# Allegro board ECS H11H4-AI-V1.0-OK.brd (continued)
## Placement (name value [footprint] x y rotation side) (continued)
R156  -  [R0402_2]  174.28 171.39 90 top
R157  -  [R0402_2]  175.36 171.39 270 top
R158  -  [R0402_2]  176.51 171.39 90 top
R159  -  [R0402_2]  177.58 171.39 90 top
R160  -  [R0402_2]  179.05 171.39 270 top
R161  -  [R0402_2]  171.04 171.33 90 top
R162  -  [R0402_2]  172.12 171.33 270 top
R163  -  [R0402_2]  163.81 171.27 270 top
R164  -  [R0402_2]  164.95 171.27 90 top
R165  -  [R0402_2]  166.09 171.27 90 top
R166  -  [R0402_2]  167.23 171.27 90 top
R167  -  [R0402_2]  168.38 171.27 270 top
R168  -  [R0402_2]  103.73 171.27 180 top
R169  -  [R0402_2]  106.59 171.27 0 top
R170  -  [R0805_2]  52.43 171.07 180 top
R171  -  [R0402_2]  103.73 170.19 0 top
R172  -  [R0805_2]  14.45 169.61 180 top
R173  -  [R0402_2]  100.56 169.61 90 top
R174  -  [R0402_2]  102.15 169.61 90 top
R175  -  [R0805_2]  170.66 169.36 0 top
R176  -  [R0402_2]  174.28 169.3 90 top
R177  -  [R0402_2]  176.89 168.98 270 top
R178  -  [R0402_2]  116.88 168.73 180 top
R179  -  [R0402_2]  133.83 168.34 0 top
R180  -  [R0402_2]  35.85 158.69 0 top
R181  -  [R0805_2]  114.85 167.14 270 top
R182  -  [R0805_2]  120.69 166.95 270 top
R183  -  [R0805_2]  140.06 166.95 270 top
R184  -  [R0805_2]  133.39 166.82 180 top
R186  -  [R0402_2]  63.86 166.19 180 top
R187  -  [R0603_2]  96.43 165.99 180 top
R188  -  [R0402_2]  98.91 165.99 180 top
R189  -  [R0805_2]  107.48 165.87 90 top
R190  -  [R0402_2]  33.57 164.47 180 top
R191  -  [R0402_2]  35.79 161.74 180 top
R192  -  [R0805_2]  133.39 164.66 180 top
R193  -  [R0402_2]  54.27 164.6 180 top
R194  -  [R0402_2]  33.57 161.23 0 top
R195  -  [R0402_2]  37.44 162.5 270 top
R196  -  [R0805_2]  130.28 164.03 270 top
R197  -  [R0805_2]  148.76 164.03 270 top
R198  -  [R0402_2]  128.75 163.33 90 top
R199  -  [R0402_2]  146.03 162.82 0 top
R200  -  [R0402_2]  33.57 162.31 180 top
R201  -  [R0402_2]  83.29 162.38 90 top
R202  -  [R0402_2]  84.37 162.38 90 top
R203  -  [R0402_2]  85.45 162.38 270 top
R204  -  [R0402_2]  86.53 162.38 90 top
R205  -  [R0402_2]  87.61 162.38 90 top
R206  -  [R0603-SHORT_2-NMNP]  4.74 162.31 270 top
R208  -  [R0805_2]  100.5 160.98 0 top
R209  -  [R0402_2]  81.51 160.6 180 top
R210  -  [R0402_2]  85.95 160.6 0 top
R211  -  [R0402_2]  89.19 160.6 180 top
R212  -  [R0805_2]  38.96 164.03 90 top
R213  -  [R0603_2]  62.65 159.71 0 top
R214  -  [R0402_2]  80.43 159.52 180 top
R215  -  [R0402_2]  87.1 159.52 180 top
R216  -  [R0402_2]  89.19 159.52 180 top
R217  -  [R0402_2]  57.95 159.33 270 top
R218  -  [R0805_2]  114.34 158.76 0 top
R219  -  [R0402_2]  88.24 158.44 180 top
R221  -  [R0402_2]  89.26 157.36 180 top
R222  -  [R0402_2]  77.83 156.91 0 top
R223  -  [R0402_2]  55.35 156.53 270 top
R224  -  [R0402_2]  56.43 156.53 270 top
R225  -  [R0402_2]  58.27 156.53 90 top
R226  -  [R0402_2]  59.35 156.53 270 top
R227  -  [R0402_2]  92.37 156.41 180 top
R228  -  [R1206]  118.47 156.41 0 top
R229  -  [R1206]  136.56 156.41 0 top
R230  -  [R0402_2]  90.27 156.28 180 top
R231  -  [R0402_2]  76.75 155.83 180 top
R232  -  [R0402_2]  91.35 155.2 180 top
R233  -  [R0402_2]  75.67 154.76 180 top
R234  -  [R0402_2]  92.43 154.12 180 top
R235  -  [R0402_2]  74.08 152.6 0 top
R236  -  [R0402_2]  7.72 152.28 90 top
R237  -  [R0402_2]  8.8 152.28 90 top
R238  -  [R0402_2]  74.08 151.52 0 top
R239  -  [R1206]  177.65 151.45 270 top
R240  -  [R0805_2]  185.9 151.14 90 top
R241  -  [R0402_2]  6.58 149.48 270 top
R242  -  [R0402_2]  10.96 145.61 270 top
R243  -  [R0402_2]  184.25 143.9 270 top
R244  -  [R0402_2]  9.88 143.45 270 top
R245  -  [R0805_2]  185.14 141.86 180 top
R246  -  [R0402_2]  10.41 141.55 0 top
R247  -  [R0402_2]  10.41 140.4 0 top
R248  -  [R0402_2]  80.37 139.77 90 top
R249  -  [R0402_2]  81.45 139.77 270 top
R250  -  [R0402_2]  86.65 139.77 270 top
R251  -  [R0402_2]  10.41 139.26 0 top
R252  -  [R0402_2]  74.91 138.37 270 top
R253  -  [R0402_2]  77.06 138.37 90 top
R254  -  [R0402_2]  78.21 138.37 270 top
R255  -  [R0805_2]  185.14 138.37 180 top
R256  -  [R0402_2]  86.97 138.18 0 top
R257  -  [R0402_2]  10.41 138.12 0 top
R258  -  [R0402_2]  162.09 137.67 180 top
R259  -  [R0402_2]  166.85 137.67 180 top
R260  -  [R0402_2]  86.97 137.1 0 top
R261  -  [R0402_2]  162.09 136.59 180 top
R262  -  [R0402_2]  164.76 136.59 180 top
R263  -  [R0603_2]  72.43 136.34 180 top
R264  -  [R0402_2]  188 136.02 90 top
R265  -  [R0805_2]  189.52 136.02 270 top
R266  -  [R0402_2]  162.09 135.51 180 top
R267  -  [R0402_2]  164.76 135.51 180 top
R268  -  [R0805_2]  185.9 135.51 90 top
R269  -  [R0402_2]  10.45 135.07 0 top
R270  -  [R0402_2]  162.09 134.44 180 top
R271  -  [R0402_2]  72.24 133.93 180 top
R272  -  [R0603_2]  82.53 133.48 0 top
R273  -  [R1206]  177.65 132.97 270 top
R274  -  [R0402_2]  10.01 132.09 270 top
R275  -  [R0402_2]  11.09 132.09 90 top
R276  -  [R0805_2]  72.81 131.2 0 top
R277  -  [R0402_2]  5.18 130.12 90 top
R278  -  [R0402_2]  184.38 126.75 270 top
R279  -  [R0402_2]  5.18 126.43 90 top
R280  -  [R0805_2]  185.27 124.72 180 top
R281  -  [R0402_2]  84.68 123.77 0 top
R282  -  [R0402_2]  5.18 122.88 90 top
R283  -  [R0402_2]  83.11 122.65 270 top
R284  -  [R0402_2]  84.68 122.5 180 top
R285  -  [R0805_2]  185.27 121.23 180 top
R286  -  [R0805_2]  189.59 119.58 180 top
R287  -  [R0402_2]  5.18 119.26 90 top
R288  -  [R0402_2]  187.3 118.75 90 top
R289  -  [R0402_2]  114.21 118.5 270 top
R290  -  [R0402_2]  115.29 118.5 90 top
R291  -  [R0402_2]  116.37 118.5 270 top
R292  -  [R0402_2]  117.45 118.48 270 top
R293  -  [R0402_2]  10.71 118.24 0 top
R294  -  [R0603_2]  42.39 116.85 90 top
R295  -  [R0402_2]  45.19 115.31 270 top
R296  -  [R0402_2]  50.62 114.2 270 top
R297  -  [R0402_2]  48.93 114.18 90 top
R298  -  [R0402_2]  52.49 114.18 90 top
R299  -  [R0402_2]  53.57 114.18 90 top
R300  -  [R0402_2]  46.74 113.84 270 top
R301  -  [R0402_2]  37.31 113.61 0 top
R302  -  [R0402_2]  37.31 112.53 0 top
R303  -  [R0402_2]  5.69 112.21 0 top
R304  -  [R0402_2]  7.72 112.21 180 top
R305  -  [R0402_2]  9.75 112.21 0 top
R306  -  [R0603_2]  39.03 111.83 270 top
R307  -  [R0402_2]  44.67 111.48 270 top
R308  -  [R0402_2]  45.73 111.48 90 top
R309  -  [R0402_2]  37.31 111.45 0 top
R310  -  [R0402_2]  49.51 111.45 90 top
R311  -  [R0402_2]  46.9 111.38 270 top
R312  -  [R0402_2]  47.98 111.38 270 top
R313  -  [R0402_2]  52.49 111.32 270 top
R314  -  [R0402_2]  53.57 111.32 90 top
R315  -  [R0402_2]  60.49 111.31 180 top
R316  -  [R0402_2]  5.18 110.56 270 top
R317  -  [R0402_2]  6.26 110.56 90 top
R318  -  [R0402_2]  11.66 110.37 90 top
R319  -  [R0402_2]  7.85 109.86 180 top
R320  -  [R0603_2]  57.94 108.91 90 top
R321  -  [R0402_2]  114.15 108.91 270 top
R322  -  [R0402_2]  32.61 107 270 top
R323  -  [R0402_2]  48.81 106.37 90 top
R324  -  [R0402_2]  49.89 106.37 90 top
R325  -  [R0402_2]  50.97 106.37 90 top
R326  -  [R0402_2]  40.93 106.3 270 top
R327  -  [R0402_2]  64.94 105.73 270 top
R328  -  [R0402_2]  185.84 105.03 270 top
R329  -  [R0402_2]  32.61 104.59 90 top
R330  -  [R0402_2]  8.99 103.7 0 top
R331  -  [R1206]  178.03 103.13 90 top
R332  -  [R0805_2]  187.05 103 180 top
R333  -  [R0402_2]  29.95 102.88 0 top
R334  -  [R0402_2]  30.65 104.46 270 top
R335  -  [R0402_2]  31.53 102.37 270 top
R336  -  [R0402_2]  32.61 102.37 270 top
R337  -  [R0402_2]  8.48 102.11 90 top
R338  -  [R0805_2]  194.92 101.61 90 top
R339  -  [R0402_2]  64.94 101.22 90 top
R340  -  [R0805_2]  185.08 100.53 180 top
R341  -  [R0402_2]  5.94 99.76 90 top
R342  -  [R0402_2]  7.02 99.76 90 top
R343  -  [R0402-SHORT_2]  28.55 99.7 270 top
R344  -  [R0402_2]  32.23 99.64 270 top
R345  -  [R0805_2]  192.32 99.64 90 top
R346  -  [R0805_2]  194.92 98.11 270 top
R347  -  [R0402_2]  190.09 97.35 180 top
R348  -  [R0805_2]  185.08 97.22 180 top
R349  -  [R0402_2]  181.27 94.68 270 top
R350  -  [R0402_2]  190.67 94.68 270 top
R351  -  [R0402_2]  191.75 94.68 270 top
R352  -  [R0402_2]  6.2 93.06 180 top
R353  -  [R0402_2]  181.84 91.26 180 top
R354  -  [R0402_2]  64.94 92.02 90 top
R355  -  [R0402_2]  191.24 91.26 180 top
R356  -  [R0402_2]  6.2 90.87 180 top
R357  -  [R0402_2]  191.24 89.99 180 top
R358  -  [R0402_2]  32.17 89.79 0 top
R359  -  [R0402_2]  191.24 88.78 180 top
R360  -  [R0402_2]  32.17 88.72 0 top
R361  -  [R0402_2]  185.01 86.43 0 top
R362  -  [R0402_2]  187.68 86.43 0 top
R363  -  [R0402_2]  185.01 85.29 0 top
R364  -  [R0402_2]  187.68 85.29 180 top
R365  -  [R0402_2]  29.38 84.63 180 top
R366  -  [R0402_2]  187.68 84.21 180 top
R367  -  [R0402_2]  22.14 82.62 90 top
R368  -  [R0402_2]  23.22 82.62 90 top
R369  -  [R0402_2]  24.49 82.62 90 top
R370  -  [R0402_2]  11.66 82.49 270 top
R371  -  [R0402_2]  31.32 82.43 180 top
R372  -  [R0402_2]  31.32 81.36 180 top
R373  -  [R0402_2]  28.7 80.59 270 top
R374  -  [R0402_2]  22.64 79.19 0 top
R375  -  [R0402_2]  22.64 78.11 180 top
R376  -  [R0402_2]  29.82 77.73 180 top
R377  -  [R0402_2]  32.23 76.97 180 top
R378  -  [R0402_2]  29.82 76.65 180 top
R379  -  [R0402_2]  22.64 75.95 180 top
R380  -  [R0402_2]  32.23 75.89 180 top
R381  -  [R0402_2]  29.82 75.57 180 top
R382  -  [R0402_2]  22.64 74.87 180 top
R383  -  [R0402_2]  32.23 74.81 0 top
R384  -  [R0402_2]  22.64 73.79 180 top
R385  -  [R0402_2]  22.64 72.71 0 top
R386  -  [R0402_2]  29.31 72.65 270 top
R387  -  [R0402_2]  41.82 72.08 90 top
R388  -  [R0402_2]  43.98 72.08 270 top
R389  -  [R0402_2]  45.06 72.08 270 top
R390  -  [R0402_2]  47.6 72.08 270 top
R391  -  [R0402_2]  49.06 72.08 270 top
R392  -  [R0402_2]  50.65 72.08 270 top
R393  -  [R0402_2]  40.74 72.07 90 top
R394  -  [R0402_2]  39.67 72.04 90 top
R395  -  [R0402_2]  51.79 72.01 270 top
R396  -  [R0402_2]  52.87 72.01 90 top
R397  -  [R0402_2]  25.57 71.89 270 top
R398  -  [R0402_2]  26.77 71.89 90 top
R399  -  [R0603_2]  38.25 71.66 90 top
R400  -  [R0402_2]  22.64 71.44 180 top
R401  -  [R0402_2]  32.23 71.32 180 top
R402  -  [R0402_2]  22.64 70.36 0 top
R403  -  [R0402_2]  25.06 69.54 270 top
R404  -  [R0402_2]  39.66 69.54 270 top
R405  -  [R0402_2]  40.74 69.54 270 top
R406  -  [R0402_2]  41.82 69.54 90 top
R407  -  [R0402_2]  44.23 69.54 270 top
R408  -  [R0603_2]  65.06 69.47 270 top
R409  -  [R0402_2]  46.39 69.35 270 top
R410  -  [R0402_2]  47.6 69.35 270 top
R411  -  [R0402_2]  49 69.35 90 top
R412  -  [R0402_2]  50.08 69.35 270 top
R413  -  [R0402_2]  51.79 69.35 270 top
R414  -  [R0402_2]  52.87 69.35 90 top
R415  -  [R0402_2]  22.64 69.28 0 top
R416  -  [R0603_2]  43.03 69.16 90 top
R417  -  [R0603_2]  35.66 68.46 180 top
R421  -  [R0402_2]  33.31 67.25 0 top
R422  -  [R0402_2]  46.39 66.93 270 top
R423  -  [R0402_2]  49 66.93 270 top
R424  -  [R0402_2]  50.08 66.93 270 top
R425  -  [R0402_2]  37.12 66.74 270 top
R426  -  [R0402_2]  38.2 66.74 270 top
R427  -  [R0402_2]  39.66 66.74 270 top
R428  -  [R0402_2]  40.74 66.74 90 top
R429  -  [R0402_2]  36.04 66.74 270 top
R430  -  [R0402_2]  33.31 66.17 180 top
R431  -  [R0402_2]  25.88 64.59 90 top
R432  -  [R0402_2]  25.88 62.49 90 top
R433  -  [R0402_2]  185.08 61.16 0 top
R434  -  [R0402_2]  8.61 60.27 90 top
R435  -  [R0402_2]  181.78 59.57 0 top
R436  -  [R0402_2]  185.08 60.08 180 top
R437  -  [R0402_2]  189.27 60.08 0 top
R438  -  [R0402_2]  45 59.44 0 top
R439  -  [R0402_2]  185.08 59 180 top
R440  -  [R0402_2]  189.27 59 180 top
R441  -  [R0402_2]  16.36 58.43 180 top
R442  -  [R0402_2]  45 58.36 180 top
R443  -  [R0402_2]  8.61 58.17 90 top
R444  -  [R0402_2]  20.8 57.92 90 top
R445  -  [R0402_2]  187.17 57.92 180 top
R446  -  [R0402_2]  56.24 57.85 270 top
R447  -  [R0402_2]  57.63 57.85 270 top
R448  -  [R0402_2]  10.33 57.35 180 top
R449  -  [R0402_2]  29.25 57.09 0 top
R450  -  [R0402_2]  187.17 56.84 180 top
R451  -  [R0402_2]  52.05 56.39 90 top
R452  -  [R0402_2]  194.48 54.93 90 top
R453  -  [R0402_2]  187.17 54.68 180 top
R454  -  [R0402_2]  189.27 54.68 180 top
R455  -  [R0402_2]  55.09 54.11 270 top
R456  -  [R0402_2]  52.49 53.6 0 top
R457  -  [R0603-SHORT_2-NMNP]  29.44 51.76 270 top
R458  -  [R0402_2]  23.6 47.95 0 top
R459  -  [R0402_2]  10.77 47.12 90 top
R460  -  [R0402_2]  23.6 45.34 0 top
R461  -  [R0402_2]  108.88 44.2 180 top
R462  -  [R0402_2]  110.97 44.2 0 top
R463  -  [R0402_2]  23.6 43.57 180 top
R464  -  [R0402_2]  23.6 41.15 0 top
R465  -  [R0402_2]  28.63 38.3 90 top
R466  -  [R0402_2]  27.47 35.44 90 top
R467  -  [R0402_2]  28.55 35.44 90 top
R468  -  [R0603_2]  47.09 34.17 180 top
R469  -  [R0402_2]  141.07 34.17 90 top
R470  -  [R0402_2]  143.74 34.17 90 top
R471  -  [R0402_2]  126.85 34.11 90 top
R472  -  [R0402_2]  129.01 34.11 270 top
R473  -  [R0402_2]  130.09 34.11 90 top
R474  -  [R0402_2]  167.11 33.15 180 top
R475  -  [R0402_2]  192 32.71 180 top
R476  -  [R0402_2]  46.9 32.39 90 top
R477  -  [R0603_2]  135.93 32.2 0 top
R478  -  [R0402_2]  148.57 32.2 90 top
R479  -  [R0402_2]  149.64 32.2 90 top
R480  -  [R0402_2]  167.11 32.07 180 top
R481  -  [R0402_2]  132.88 31.82 90 top
R482  -  [R0402_2]  192 31.63 180 top
R483  -  [R0402_2]  50.52 30.8 0 top
R484  -  [R0402_2]  192 30.55 180 top
R485  -  [R0402_2]  194.86 30.55 180 top
R486  -  [R0402_2]  135.55 30.49 0 top
R487  -  [R0402_2]  138.34 30.42 0 top
R488  -  [R0805_2]  41.89 30.23 270 top
R489  -  [R0805_2]  127.04 30.04 270 top
R490  -  [R0402_2]  50.52 29.72 180 top
R491  -  [R0402_2]  167.11 29.66 180 top
R492  -  [R0402_2]  25.63 29.47 270 top
R493  -  [R0402_2]  192 29.47 180 top
R494  -  [R0402_2]  194.86 29.47 180 top
R495  -  [R0402_2]  138.34 29.34 180 top
R496  -  [R0402_2]  96.24 29.15 90 top
R497  -  [R0402_2]  94.65 28.58 0 top
R498  -  [R0402_2]  192 28.39 180 top
R499  -  [R0402_2]  194.86 28.39 180 top
R500  -  [R0402_2]  106.91 28.33 270 top
R501  -  [R0402_2]  107.99 28.33 90 top
R502  -  [R0402_2]  109.64 28.33 270 top
R503  -  [R0402_2]  50.52 28.26 0 top
R504  -  [R0402_2]  138.34 28.2 0 top
R505  -  [R0402_2]  162.22 28.14 0 top
R506  -  [R0402_2]  25.63 27.37 90 top
R507  -  [R0402_2]  26.71 27.37 270 top
R508  -  [R0402_2]  192 27.31 180 top
R509  -  [R0402_2]  194.86 27.31 180 top
R510  -  [R0402_2]  135.55 27.06 180 top
R511  -  [R0402_2]  167.11 27.06 180 top
R512  -  [R0402_2]  164.38 25.98 180 top
R513  -  [R0402_2]  167.11 25.98 180 top
R514  -  [R0402_2]  138.34 25.91 0 top
R515  -  [R0402_2]  194.86 25.91 0 top
R516  -  [R0402_2]  192 25.72 0 top
R517  -  [R0402_2]  26.71 25.28 90 top
R518  -  [R0402_2]  164.38 24.9 180 top
R519  -  [R0402_2]  167.11 24.9 0 top
R520  -  [R0402_2]  144.76 24.83 270 top
R521  -  [R0402_2]  146.09 24.83 270 top
R522  -  [R0805_2]  138.98 24.2 0 top
R523  -  [R0402_2]  194.48 24.14 90 top
R524  -  [R0402_2]  160 24.01 270 top
R525  -  [R0805_2]  45.95 23.56 270 top
R526  -  [R0402_2]  164.38 23.82 0 top
R527  -  [R0402_2]  146.09 22.74 270 top
R528  -  [R0402_2]  164.38 22.74 0 top
R529  -  [R0402_2]  28.55 22.23 0 top
R530  -  [R0402_2]  31.98 24.45 180 top
R531  -  [R0402_2]  160 21.91 90 top
R532  -  [R0402_2]  133.2 21.85 0 top
R533  -  [R0402_2]  30.14 21.66 90 top
R534  -  [R0603-SHORT_2]  166.6 21.53 0 top
R535  -  [R0805_2]  130.09 21.47 270 top
R536  -  [R0402_2]  146.09 20.64 270 top
R537  -  [R0402_2]  191.49 20.58 270 top
R538  -  [R0402_2]  167.11 20.33 0 top
R539  -  [R0402_2]  96.05 19.69 0 top
R540  -  [R0402_2]  138.66 19.69 90 top
R541  -  [R0402_2]  139.74 19.69 90 top
R542  -  [R0402_2]  189.33 18.74 0 top
R543  -  [R0402_2]  132.63 18.67 90 top
R544  -  [R0402_2]  167.11 18.17 180 top
R545  -  [R0402_2]  191.49 18.1 270 top
R546  -  [R0402_2]  189.33 17.6 0 top
R547  -  [R0402_2]  11.79 16.58 90 top
R548  -  [R0402_2]  133.71 16.58 270 top
R549  -  [R0402_2]  100.31 16.33 90 top
R550  -  [R0402_2]  189.33 15.18 0 top
R551  -  [R0402_2]  133.71 14.48 90 top
R552  -  [R0603_2]  86.78 14.36 180 top
R553  -  [R0603_2]  96.94 13.85 90 top
R554  -  [R0402_2]  67.48 13.66 0 top
R555  -  [R0402_2]  173.74 13.59 270 top
R556  -  [R0402_2]  98.65 13.47 90 top
R557  -  [R0402_2]  100.43 13.47 90 top
R558  -  [R0402_2]  101.51 13.47 90 top
R559  -  [R0402_2]  102.59 13.47 270 top
R560  -  [R0402_2]  104.69 13.47 90 top
R561  -  [R0402_2]  106.46 13.47 90 top
R562  -  [R0402_2]  191.05 13.47 90 top
R563  -  [R0402_2]  192.13 13.47 90 top
R564  -  [R0402_2]  194.29 13.47 90 top
R565  -  [R0402_2]  63.03 14.04 180 top
R566  -  [R0402_2]  63.03 12.91 0 top
R567  -  [R0402_2]  149.45 13.21 270 top
R568  -  [R0402_2]  133.2 12.9 180 top
R569  -  [R0805_2]  50.46 12.58 180 top
R570  -  [R0402_2]  47.09 12.13 180 top
R571  -  [R0402_2]  61.19 13.4 90 top
R572  -  [R0402_2]  195.36 11.37 90 top
R573  -  [R0402_2]  137.33 11.31 0 top
R574  -  [R0402_2]  174.35 11.12 90 top
R575  -  [R0402_2]  177.84 11.12 270 top
R576  -  [R0402_2]  178.92 11.12 270 top
R577  -  [R0402_2]  180 11.12 270 top
R578  -  [R0402_2]  181.08 11.12 270 top
R579  -  [R0402_2]  182.16 11.12 270 top
R580  -  [R0402_2]  183.25 11.12 270 top
R581  -  [R0402_2]  138.91 10.86 90 top
R582  -  [R0402_2]  141.07 10.86 90 top
R583  -  [R0805_2]  53.63 10.55 180 top
R584  -  [R0402_2]  60.05 13.4 270 top
R585  -  [R0402_2]  137.33 10.23 0 top
R586  -  [R0402_2]  18.39 9.72 0 top
R587  -  [R0402_2]  58.9 13.4 270 top
R588  -  [R0603_2]  112.62 8.64 270 top
R589  -  [R0603-SHORT_2]  182.98 8.45 90 top
R590  -  [R0402_2]  107.93 8.26 90 top
R591  -  [R0402_2]  109 8.26 270 top
R592  -  [R0402_2]  110.08 8.26 90 top
R593  -  [R0402_2]  118.28 8.26 90 top
R594  -  [R0402_2]  120.82 8.26 90 top
R595  -  [R0402_2]  122.97 8.26 270 top
R596  -  [R0402_2]  124.05 8.26 270 top
R597  -  [R0402_2]  126.21 8.26 270 top
R598  -  [R0402_2]  135.74 8.26 90 top
R599  -  [R0402_2]  139.55 8.26 90 top
R600  -  [R0402_2]  140.63 8.26 90 top
R601  -  [R0603_2]  189.84 8.01 90 top
R602  -  [R0402_2]  53.82 6.8 0 top
R603  -  [R0603_2]  97.57 7.88 180 top
R604  -  [R0603_2]  100.43 7.88 0 top
R605  -  [R0402_2]  102.91 7.88 180 top
R606  -  [R0402_2]  114.4 7.88 0 top
R607  -  [R0402_2]  137.9 7.82 0 top
R608  -  [R0603_2]  62.21 6.57 180 top
R609  -  [R0402_2]  189.71 5.53 270 top
R610  -  [R0603_2]  96.81 4.96 270 top
R611  -  [R0805_2]  47.09 4.58 0 top
R612  -  [R2512_1]  65.06 3.88 180 top
R613  -  [R0402_2]  189.71 3.43 90 top
R614  -  [R0402_2]  78.97 2.93 0 top
R615  -  [R0402-SHORT_2-NMNP]  29.88 101.35 180 top
R616  -  [R0402_2]  68.43 7.44 270 top
R617  -  [R0402_2]  16.61 36.26 90 top
R618  -  [R0402_2]  13.56 33.98 270 top
R619  -  [R0402_2]  17.76 36.26 270 top
R620  -  [R0402_2]  15.47 36.26 270 top
R621  -  [R0402_2]  18.52 34.36 180 top
R622  -  [R0603_2]  62.21 7.94 180 top
R623  -  [R0402_2]  62.33 10.61 0 top
R624  -  [R0402_2]  57.25 13.02 0 top
R625  -  [R0402_2]  57.25 11.88 0 top
RJ1  -  [RJ3_0402]  19.98 173.3 180 top
RJ2  -  [RJ3_0402]  40.93 172.73 180 top
RJ3  -  [RJ3_0402]  27.6 67.44 270 top
RJ4  -  [RJ3_0402]  18.33 11.05 0 top
RJ5  -  [RJ3_0402]  30.02 67.68 90 top
RJ6  -  [RJ3_0402]  28.82 67.68 90 top
RJ7  -  [RJ3_0402]  31.17 67.68 90 top
RN1  -  [8P4R-0402]  173.33 200.98 90 top
RN2  -  [8P4R-0402]  136.82 195.9 270 top
RN3  -  [8P4R]  140.44 195.9 270 top
RN4  -  [8P4R-0402]  136.82 192.09 270 top
RN5  -  [8P4R]  140.44 192.09 270 top
RN6  -  [8P4R]  91.16 188.03 0 top
RN7  -  [8P4R]  94.97 188.03 0 top
RN8  -  [8P4R]  87.22 185.81 0 top
RN9  -  [8P4R]  54.39 179.77 270 top
RN10  -  [8P4R-0402]  192.63 59.12 0 top
RN11  -  [8P4R]  11.02 34.17 0 top
RN12  -  [8P4R]  17.18 29.34 90 top
RN13  -  [8P4R]  15.79 25.16 90 top
RN14  -  [8P4R]  15.79 21.09 90 top
RN15  -  [8P4R-0402]  151.8 16.2 180 top
RN16  -  [8P4R-0402]  155.99 16.2 180 top
RN17  -  [8P4R-0402]  160 16.2 180 top
RN18  -  [8P4R-0402]  151.8 13.47 180 top
RN19  -  [8P4R-0402]  155.99 13.47 180 top
RN20  -  [8P4R-0402]  160 13.47 180 top
RN21  -  [8P4R-0402]  163.23 13.47 180 top
RN22  -  [8P4R-0402]  182.16 5.59 90 top
ROM1  -  [SOP8_W150_PT50]  186.41 6.23 180 top
RT1  -  [R0402_2]  140.95 169.74 90 top
RT2  -  [R0402_2]  150.15 151.2 90 top
RT3  -  [R0402_2]  188.19 132.28 180 top
RT4  -  [R0402_2]  177.39 118.43 0 top
SATA1  -  [SATA3_7P-HI-TOP]  83.41 29.22 180 top
SATA2  -  [SATA3_7P-HI-TOP]  59.98 29.28 180 top
SATA_PWR  -  [CON6X1_2D5MM-PINREX]  103.54 24.33 0 top
SC1  +  [C7343_1]  122.29 119.18 180 bottom
SC2  +  [C7343_1]  132.06 114.24 180 bottom
SHK*  -  [unnamed#3]  48.78 89.18 90 top
SP1  -  [SHORT2-NMNP]  104.81 172.73 270 top
SP2  -  [SHORT2-NMNP]  106.08 172.73 270 top
SP3  -  [SHORT2-NMNP]  129.26 156.91 270 top
SP4  -  [SHORT2-NMNP]  146.09 156.91 270 top
SP5  -  [SHORT2-NMNP]  129.26 155.14 90 top
SP6  -  [SHORT2-NMNP]  146.09 155.14 90 top
SP7  -  [SHORT2-NMNP]  81.38 142.75 180 top
SP8  -  [SHORT2-NMNP]  176.11 141.87 0 top
SP9  -  [SHORT2-NMNP]  177.9 141.86 180 top
SP10  -  [SHORT2-NMNP]  81.38 141.48 180 top
SP11  -  [SHORT2-NMNP]  176.19 123.01 0 top
SP12  -  [SHORT2-NMNP]  177.97 123.01 180 top
SP13  -  [SHORT2-NMNP]  176.12 113.8 0 top
SP14  -  [SHORT2-NMNP]  177.9 113.8 180 top
SP15  -  [SHORT2-NMNP]  75.98 109.86 270 top
SP16  -  [SHORT2-NMNP]  54.78 106.18 270 top
SP17  -  [SHORT2-NMNP]  56.05 106.18 270 top
SP18  -  [SHORT2-NMNP]  24.21 90.67 270 top
SP19  -  [SHORT2-NMNP]  42.9 59.44 180 top
SP20  -  [SHORT2-NMNP]  191.11 23.69 90 top
SPIROM1  -  [SOP8_W210_PT50_SPI_1]  36.11 57.73 90 top
STP1  -  [TP30_SMD]  114.3 129.66 180 bottom
STP2  -  [TP30_SMD]  113.59 125.01 180 bottom
STP3  -  [TP30_SMD]  116.26 125.39 180 bottom
STP4  -  [TP30_SMD]  112.17 122.24 180 bottom
STP5  -  [TP30_SMD]  140.21 112.39 180 bottom
STP6  -  [TP30_SMD]  41.82 102.43 270 bottom
STP7  -  [TP30_SMD]  54.71 99.79 90 bottom
STP8  -  [TP30_SMD]  54.2 98.11 90 bottom
STP9  -  [TP30_SMD]  51.71 96.72 90 bottom
STP10  -  [TP30_SMD]  43.1 92.02 180 bottom
STP11  -  [TP30_SMD]  35.99 92.6 90 bottom
STP12  -  [TP30_SMD]  43.54 86.49 180 bottom
STP13  -  [TP30_SMD]  41.76 86.48 180 bottom
STP14  -  [TP30_SMD]  36.27 85.67 180 bottom
STP15  -  [TP30_SMD]  43.54 84.71 90 bottom
STP16  -  [TP30_SMD]  40.74 84.21 90 bottom
STP17  -  [TP30_SMD]  34.47 84.12 270 bottom
STP18  -  [TP30_SMD]  38.18 84.93 180 bottom
STP19  -  [TP30_SMD]  42.39 83.38 90 bottom
STP20  -  [TP30_SMD]  35.54 79.52 180 bottom
STP21  -  [TP30_SMD]  42.39 81.6 90 bottom
STP22  -  [TP30_SMD]  31.09 79.09 180 bottom
STP23  -  [TP30_SMD]  42.27 79.88 90 bottom
STP24  -  [TP30_SMD]  49.91 77.34 180 bottom
STP25  -  [TP30_SMD]  40.13 81.86 180 bottom
STP26  -  [TP30_SMD]  42.29 78.1 90 bottom
STP27  -  [TP30_SMD]  46.86 75.99 270 bottom
STP28  -  [TP30_SMD]  28.3 72.97 180 bottom
STP29  -  [TP30_SMD]  44.3 69.86 270 bottom
STP30  -  [TP30_SMD]  24.21 66.79 180 bottom
STP31  -  [TP30_SMD]  176.64 30.19 270 bottom
STP32  -  [TP30_SMD]  104.98 27.55 180 bottom
STP33  -  [TP30_SMD]  178.66 15.94 180 bottom
STP_VGA  -  [TP30_SMD]  52.78 72.48 270 bottom
SZ1  -  [JOPEN_200X60_NMNP]  182.47 162.06 0 bottom
TCM  -  [J10X2_TPM_4P]  129.32 4.58 0 top
TP1  -  [TP30_SMD]  111.33 195.83 0 top
TP2  -  [TP30_SMD]  113.11 195.83 0 top
TP3  -  [TP30_SMD]  23.09 178.82 0 top
TP4  -  [TP30_SMD]  45.01 109.87 270 top
TP5  -  [TP30_SMD]  178.66 94.37 0 top
TP6  -  [TP30_SMD]  178.33 12.67 0 top
U1  -  [SOT23_6P_2]  118.21 199.52 90 top
U2  -  [SOT23_6P_2]  123.86 199.52 90 top
U3  -  [FPC_4P10_R_1]  143.87 195.9 270 top
U4  -  [QFN32_PT04_NCP81102]  107.61 195.46 90 top
U5  -  [FPC_4P10_R_1]  143.87 192.09 270 top
U6  -  [FPC_4P10_R_1]  91.1 191.2 0 top
U7  -  [FPC_4P10_R_1]  94.97 191.2 0 top
U8  -  [SOT23_6P_2]  87.22 190.12 0 top
U9  -  [SOT23_6P_2]  141.01 186.89 0 top
U10  -  [QFN52_PT04_NCP61X1S_1]  170.03 181.17 90 top
U11  -  [SOT23_6P_2]  69.84 180.11 180 top
U12  -  [SOT23_6P_2]  74.11 180.11 180 top
U13  -  [SOT23_6P_2]  58.87 179.8 270 top
U14  -  [PSOP8_W150_PT50_PAD-UP7719B_1]  93.7 178.38 270 top
U15  -  [SOT23_5P_1]  46.97 171.84 270 top
U16  -  [DFN8_NCP5359A_1]  118.02 166.69 180 top
U17  -  [DFN8_NCP5359A_1]  137.45 166.69 180 top
U18  -  [QFN32_PT04_UP1740Q_3]  102.85 164.79 270 top
U19  -  [QFN32_PT04_NCP81102]  59.6 164.22 270 top
U21  -  [DFN8_NCP5359A_1]  188.32 139.26 0 top
U22  -  [QFN32_PT04_UP1740Q_2]  77.45 133.61 270 top
U23  -  [DFN8_NCP5359A_1]  188.32 122.05 0 top
U24  -  [TDFN14_PT04_2D5X0D9MM]  65.32 114.12 270 top
U25  -  [DFN8_NCP5359A_1]  189.01 99.38 0 top
U26  -  [SOP8_W150_PT50_3D7X2D6MM]  6.71 82.75 0 top
U27  -  [SOT23_8P_1]  14.01 46.74 180 top
U28  -  [SOT23_6P_2]  11.02 37.98 180 top
U29  -  [SOP8_W150_PT50_3X2D5MM]  101.38 30.3 90 top
U30  -  [SOT23_6P_2]  13.37 29.28 90 top
U31  -  [QFN32_PT04_UP1740Q_3]  45.7 28.52 180 top
U32  -  [QFN32_PT04_UP1740Q_3]  130.85 27.95 180 top
U33  -  [TSSOP20_W170_PT065]  153.77 27.06 0 top
U34  -  [FPC_4P10_R_1]  12.36 25.15 270 top
U35  -  [LQFP128_PT04]  177.84 23.5 0 top
U36  -  [FPC_4P10_R_1]  12.36 21.02 270 top
U37  -  [PSOP8_W150_PT50_PAD-UP7719B_1]  22.52 14.1 0 top
U38  -  [DFN10_PT05_NCP1593]  57.51 8.64 270 top
U39  -  [QFN24_PT04_G5383A_1]  39.73 159.26 0 top
USB2_LAN  -  [RJ45_USB_22P-ICOTHING_2]  71.66 197.17 180 top
USB3F  -  [CON10X2_2MM_20P_USB3_1]  7.66 21.02 90 top
USB3X2  -  [USB3_18P4R-LOTES-SHORTBODY_1]  91.85 203.33 180 top
VGA  -  [D-SUB_15P-HDR-HT]  121.1 206.69 0 top
X1  -  [CRYSTAL_PT4D88MM-AT49_2]  69.57 102.69 270 top
Y1  -  [CRYSTAL_1]  71.92 168.79 0 top
Y2  -  [ETXTALS-SPAD_1]  28.68 91.38 270 top
Z1  -  [JOPEN_200X60_NMNP]  182.47 162.06 180 top

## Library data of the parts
ATX_12V = ATX_PWR_4P_2
ATX_POWER = ATX_PWR_12P-RUIYE_2
AUDIO = AUDIO_JACK_13P-COLAY_2
BAT1 = BATTERY_HOLDER_CR2032-LOTES
BIOS_WP CLR_CMOS ME_DISABLE = J3X1
BZ = BUZZER_1
C1-C8 C12-C32 C38-C57 C59 C61-C66 C69-C75 C77-C81 C83 C84 C86-C101 C103-C109 C111-C114 C116-C118 C120-C130 C135 C137 C139 C140 C142-C154 C156-C163 C165 C168-C171 C173 C174 C178 C179 C181-C185 C190-C194 C196 C198-C203 C206 C208 C211-C214 C216 C218 C220 C221 C229-C248 C251 C254 C256 C258 C259 C262 C263 C266 C275 C276 C282 C283 C292 C294 C296 C303-C310 C316 C324 C326-C336 C338 C339 C341 C343-C347 C350-C361 C363 C367 C369-C371 C373 C374 C377 C381 C384-C392 C396 C399-C401 C403-C405 C408-C419 C421 C422 C424-C426 C428-C439 C443 C444 C452 C453 C455-C457 C461-C463 C465-C474 C477-C496 C498-C502 C504-C509 C511 C515-C528 C531-C540 C542 C545 C546 C550 C552-C566 C568 C570-C575 C577-C581 C583 C584 C586-C592 C594-C598 C600 = C0402_2
C9 C11 C33-C37 C58 C60 C68 C76 C85 C110 C115 C132-C134 C138 C141 C175-C177 C186-C189 C197 C204 C205 C207 C209 C210 C217 C222-C224 C249 C250 C252 C253 C255 C257 C261 C264 C267-C274 C278-C281 C285 C287-C291 C295 C298-C302 C311-C315 C318-C323 C325 C348 C349 C362 C365 C366 C368 C372 C375 C376 C378-C380 C382 C383 C393 C407 C423 C441 C442 C449-C451 C458-C460 C476 C510 C530 C541 C544 C547-C549 C567 C593 = C0805_2
C10 C67 C82 C102 C119 C131 C166 C167 C228 C260 C265 C337 C340 C342 C364 C394 C395 C427 C440 C445 C446 C454 C497 C529 C543 C551 C569 C576 C582 C585 = C0603_2
C136 C155 C164 C195 C215 C219 C225-C227 C277 C284 C286 C293 C297 C317 C397 C398 C402 C406 C420 C447 C448 C464 C475 C503 C512-C514 = C0603_4D7UF
CHOKE1-CHOKE14 L13 L14 L26 L27 = WCM2012F2S_1
CMK1 CMK2 = CMM21_1
CN1-CN4 = 8P4C
CODEC = LQFP48
COM = J5X2_PANEL
CPU = LGA1151-INTEL
CPU_FAN = J4X1_WAFER
D1 D3-D6 D11 D15 D19 D24 D25 = SOT23_3L
D2 D14 D20 QN2 QN3 = SOT23_2MM_2
D7-D10 D13 = SOD_523
D12 Q6 Q8-Q12 Q14 Q15 Q21-Q24 Q30-Q35 Q37 Q38 Q40 Q43-Q47 Q49-Q52 Q56-Q60 Q63 Q85 QN1 QN7 = SOT23_GDS_2
D16 = BAT54_132_2
D17 D18 D21-D23 D26 D27 = SOD_123_2
DIMM1 DIMM2 = DDR4_288P_1
EC1 EC2 = EC2_4_H5MM
EC3-EC6 EC21 EC22 EC27 = EC2D5_6D3_H11MM
EC7-EC9 EC19 EC26 = EC3D5_8_H11MM_1P
EC11-EC18 EC20 EC28-EC30 = EC2D5_6D3_H8MM
EC23 EC24 = EC2D5_6D3_H9MM
EC25 = EC3D5_8_H13MM_1P
F1 = FUSE_SMD_1
F_AUDIO = J5X2_AUDIO_1
F_PANEL = J7X2_PANEL_10P
F_USB = J5X2_USB_1394
FB1-FB3 L3 L7 = FB0402_2
FB4 L1 L2 L4-L6 L8-L12 L25 L31 = FB0603_2
FB5-FB7 L30 PFB1-PFB5 = FB0805_2
H1-H4 = HOLE8_5
HDMI = HDMI_19P-F_SMD-HIGH-TOP_5
INT_SPK = J4X2_4P
L15 = CHOKE-APL0806P-R60M
L16 = L0805_2
L17 L18 L21 L23 L24 = CHOKE_R30_PT6D3X1D4MM_1
L19 L28 L29 = CHOKE_1R0M_1
L20 = CHOKE_3R3M_PT5MM_SMD
L22 = CHOKE_PT6D2MM_SMD_2P
L32 = CHOKE_2R2M_PT6D6X6D6MM
LPT = J13X2_LPT_1
PCH1 = BGA837-INTEL_1
PCIE16X = PCIE_X16_164P_4
PSKM = KB_MS-MINI-DIN_1
Q1-Q5 Q7 = SOT363_6P
Q13 Q16-Q20 Q25-Q29 Q36 Q39 Q41 Q42 Q48 Q53-Q55 Q61 Q62 Q64-Q69 QN5 = SOT23_BCE_2
Q84 Q86 = SOT363_PT065_MOSFET
QCGH1 QCGH2 QCGL1-QCGL4 QCH1-QCH3 QCL1-QCL6 QD5H1 QD5L1 = Q_TDSON8-GDS-4
QN4 = DFN6_PT065_SM2203NSQG
R1-R22 R24-R60 R62-R64 R66-R104 R106-R133 R135-R169 R171 R173 R174 R176-R180 R186 R188 R190 R191 R193-R195 R198-R205 R209-R211 R214-R217 R219 R221-R227 R230-R238 R241-R244 R246-R254 R256-R262 R264 R266 R267 R269-R271 R274 R275 R277-R279 R281-R284 R287-R293 R295-R305 R307-R319 R321-R330 R333-R337 R339 R341 R342 R344 R347 R349-R398 R400-R407 R409-R415 R421-R456 R458-R467 R469-R476 R478-R487 R490-R521 R523 R524 R526-R533 R536-R551 R554-R568 R570-R582 R584-R587 R590-R600 R602 R605-R607 R609 R613 R614 R616-R621 R623-R625 RT1-RT4 = R0402_2
R23 R170 R172 R175 R181-R184 R189 R192 R196 R197 R208 R212 R218 R240 R245 R255 R265 R268 R276 R280 R285 R286 R332 R338 R340 R345 R346 R348 R488 R489 R522 R525 R535 R569 R583 R611 = R0805_2
R61 R65 R534 R589 = R0603-SHORT_2
R105 R134 R206 R457 = R0603-SHORT_2-NMNP
R187 R213 R263 R272 R294 R306 R320 R399 R408 R416 R417 R468 R477 R552 R553 R588 R601 R603 R604 R608 R610 R622 = R0603_2
R228 R229 R239 R273 R331 = R1206
R343 = R0402-SHORT_2
R612 = R2512_1
R615 = R0402-SHORT_2-NMNP
RJ1-RJ7 = RJ3_0402
RN1 RN2 RN4 RN10 RN15-RN22 = 8P4R-0402
RN3 RN5-RN9 RN11-RN14 = 8P4R
ROM1 = SOP8_W150_PT50
SATA1 SATA2 = SATA3_7P-HI-TOP
SATA_PWR = CON6X1_2D5MM-PINREX
SC1 SC2 = C7343_1
SP1-SP20 = SHORT2-NMNP
SPIROM1 = SOP8_W210_PT50_SPI_1
STP1-STP33 STP_VGA TP1-TP6 = TP30_SMD
SZ1 Z1 = JOPEN_200X60_NMNP
TCM = J10X2_TPM_4P
U1 U2 U8 U9 U11-U13 U28 U30 = SOT23_6P_2
U3 U5-U7 U34 U36 = FPC_4P10_R_1
U4 U19 = QFN32_PT04_NCP81102
U10 = QFN52_PT04_NCP61X1S_1
U14 U37 = PSOP8_W150_PT50_PAD-UP7719B_1
U15 = SOT23_5P_1
U16 U17 U21 U23 U25 = DFN8_NCP5359A_1
U18 U31 U32 = QFN32_PT04_UP1740Q_3
U22 = QFN32_PT04_UP1740Q_2
U24 = TDFN14_PT04_2D5X0D9MM
U26 = SOP8_W150_PT50_3D7X2D6MM
U27 = SOT23_8P_1
U29 = SOP8_W150_PT50_3X2D5MM
U33 = TSSOP20_W170_PT065
U35 = LQFP128_PT04
U38 = DFN10_PT05_NCP1593
U39 = QFN24_PT04_G5383A_1
USB2_LAN = RJ45_USB_22P-ICOTHING_2
USB3F = CON10X2_2MM_20P_USB3_1
USB3X2 = USB3_18P4R-LOTES-SHORTBODY_1
VGA = D-SUB_15P-HDR-HT
X1 = CRYSTAL_PT4D88MM-AT49_2
Y1 = CRYSTAL_1
Y2 = ETXTALS-SPAD_1

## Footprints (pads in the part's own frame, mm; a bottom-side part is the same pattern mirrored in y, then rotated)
8P4C
  rect 0.61x1.143 smd: 1(-1.219,-0.826) 2(-1.219,0.826) 7(1.219,-0.826) 8(1.219,0.826)
  rect 0.508x1.143 smd: 3(-0.406,-0.826) 4(-0.406,0.826) 5(0.406,-0.826) 6(0.406,0.826)
8P4R
  rect 0.61x1.143 smd: 1(-1.219,-0.826) 2(-1.219,0.826) 7(1.219,-0.826) 8(1.219,0.826)
  rect 0.508x1.143 smd: 3(-0.406,-0.826) 4(-0.406,0.826) 5(0.406,-0.826) 6(0.406,0.826)
8P4R-0402
  rect 0.432x0.864 smd: 1(-0.826,-0.638) 2(-0.826,0.638) 7(0.826,-0.638) 8(0.826,0.638)
  rect 0.279x0.864 smd: 3(-0.25,-0.638) 4(-0.25,0.638) 5(0.25,-0.638) 6(0.25,0.638)
ATX_PWR_4P_2
  rect 2.286x2.286 hole 1.422: 1(-2.1,2.8)
  round 2.286 hole 1.422: 2(2.1,2.8) 3(-2.1,-2.8) 4(2.1,-2.8)
ATX_PWR_12P-RUIYE_2
  rect 1.905x1.905 hole 1.397: 1(-10.5,2.75)
  round 1.905 hole 1.397: 2(-6.3,2.75) 3(-2.1,2.75) 4(2.1,2.75) 5(6.3,2.75) 6(10.5,2.75) 7(-10.5,-2.75) 8(-6.3,-2.75) 9(-2.1,-2.75) 10(2.1,-2.75) 11(6.3,-2.75) 12(10.5,-2.75)
AUDIO_JACK_13P-COLAY_2
  round 2.337 hole 2.337 unplated: (0,5.275)
  oval 1.473x1.575 hole 1.016x1.118: 5(0,1.425) 11(5,1.425) 12(2.5,1.425) 13(-2.5,1.425) 14(-5,1.425) 21(3.75,-3.575) 22(1.25,-3.575) 23(-1.25,-3.575) 24(-3.75,-3.575) 31(3.75,-8.575) 32(1.25,-8.575) 33(-1.25,-8.575) 34(-3.75,-8.575)
  round 2.692 hole 2.337: G1(-6.05,5.275) G2(6.05,5.275) G3(-6.05,-6.025) G4(6.05,-6.025)
BAT54_132_2
  rect 1.016x1.016 smd: 1(-1.016,-1.143) 2(1.016,-1.143) 3(0,1.143)
BATTERY_HOLDER_CR2032-LOTES
  round 1.524 hole 1.016: N(0,7.71)
  round 1.626 hole 1.118: P(0,-12.29)
BGA837-INTEL_1
  round 1.016 smd: (-12.548,-12.548) (12.636,12.764)
  round 0.305 smd: A2(10.46,-10.814) A3(9.959,-10.814) A4(9.459,-10.814) A42(-9.459,-10.814) A43(-9.959,-10.814) A44(-10.46,-10.814) AA17(3.099,-0.775) AA18(2.324,-0.775) AA20(1.549,-0.775) AA21(0.775,-0.775) AA23(0,-0.775) AA25(-0.775,-0.775) AA26(-1.549,-0.775) AA28(-2.324,-0.775) AA29(-3.099,-0.775) AB7(8.175,-0.667) AB8(7.413,-0.667) AB10(6.651,-0.667) AB11(5.889,-0.667) AB13(5.127,-0.667) AB14(4.365,-0.667) AB15(3.807,-0.667) AB31(-3.807,-0.667) AB32(-4.365,-0.667) AB33(-5.127,-0.667) AB35(-5.889,-0.667) AB36(-6.651,-0.667) AB38(-7.413,-0.667) AB39(-8.175,-0.667) AC17(3.099,0) AC18(2.324,0) AC20(1.549,0) AC21(0.775,0) AC23(0,0) AC25(-0.775,0) AC26(-1.549,0) AC28(-2.324,0) AC29(-3.099,0) AD7(8.175,0.667) AD8(7.413,0.667) AD10(6.651,0.667) AD11(5.889,0.667) AD13(5.127,0.667) AD14(4.365,0.667) AD15(3.807,0.667) AD31(-3.807,0.667) AD32(-4.365,0.667) AD33(-5.127,0.667) AD35(-5.889,0.667) AD36(-6.651,0.667) AD38(-7.413,0.667) AD39(-8.175,0.667) AE17(3.099,0.775) AE18(2.324,0.775) AE20(1.549,0.775) AE21(0.775,0.775) AE23(0,0.775) AE25(-0.775,0.775) AE26(-1.549,0.775) AE28(-2.324,0.775) AE29(-3.099,0.775) AF17(3.099,1.549) AF18(2.324,1.549) AF20(1.549,1.549) AF21(0.775,1.549) AF23(0,1.549) AF25(-0.775,1.549) AF26(-1.549,1.549) AF28(-2.324,1.549) AF29(-3.099,1.549) AG7(8.175,1.772) AG8(7.413,1.772) AG10(6.651,1.772) AG11(5.889,1.772) AG13(5.127,1.772) AG14(4.365,1.772) AG15(3.807,1.772) AG31(-3.807,1.772) AG32(-4.365,1.772) AG33(-5.127,1.772) AG35(-5.889,1.772) AG36(-6.651,1.772) AG38(-7.413,1.772) AG39(-8.175,1.772) AH17(3.099,2.324) AH18(2.324,2.324) AH20(1.549,2.324) AH21(0.775,2.324) AH23(0,2.324) AH25(-0.775,2.324) AH26(-1.549,2.324) AH28(-2.324,2.324) AH29(-3.099,2.324) AJ7(8.074,2.953) AJ8(7.312,2.953) AJ10(6.55,2.953) AJ11(5.788,2.953) AJ13(5.026,2.953) AJ14(4.315,2.953) AJ15(3.807,2.953) AJ17(3.099,3.099) AJ18(2.324,3.099) AJ20(1.549,3.099) AJ21(0.775,3.099) AJ23(0,3.099) AJ25(-0.775,3.099) AJ26(-1.549,3.099) AJ28(-2.324,3.099) AJ29(-3.099,3.099) AJ31(-3.807,2.953) AJ32(-4.365,2.953) AJ33(-5.127,2.953) AJ35(-5.889,2.953) AJ36(-6.651,2.953) AJ38(-7.413,2.953) AJ39(-8.175,2.953) AL7(8.074,4.071) AL8(7.312,4.071) AL10(6.55,4.071) AL11(5.788,4.071) AL13(5.026,4.071) AL17(2.953,3.807) AL19(1.772,3.807) AL22(0.667,3.807) AL24(-0.667,3.807) AL27(-1.772,3.807) AL29(-2.953,3.807) AL32(-4.34,4.096) AL33(-5.102,4.096) AL35(-5.864,4.096) AL36(-6.626,4.096) AL38(-7.388,4.096) AL39(-8.15,4.096) AM15(4.096,4.34) AM17(2.953,4.365) AM19(1.772,4.365) AM22(0.667,4.365) AM24(-0.667,4.365) AM27(-1.772,4.365) AM29(-2.953,4.315) AN7(8.023,5.036) AN8(7.261,4.985) AN10(6.499,4.985) AN11(5.753,5.026) AN15(4.096,5.102) AN17(2.953,5.127) AN19(1.772,5.127) AN22(0.667,5.127) AN24(-0.667,5.127) AN27(-1.772,5.127) AN29(-2.953,5.026) AN31(-4.071,5.026) AN36(-6.47,5.087) AN38(-7.232,5.087) AN39(-7.994,5.087) AP11(6.04,5.551) AR7(7.999,6.037) AR9(7.084,6.077) AR15(4.096,5.864) AR17(2.953,5.889) AR19(1.772,5.889) AR22(0.667,5.889) AR24(-0.667,5.889) AR27(-1.772,5.889) AR29(-2.953,5.788) AR31(-4.071,5.788) AR33(-5.026,5.753) AR34(-5.551,6.04) AR38(-7.396,6.068) AR39(-8.158,6.068) AT9(6.938,6.713) AT10(6.311,6.663) AT13(5.087,6.47) AT15(4.096,6.626) AT17(2.953,6.651) AT19(1.772,6.651) AT22(0.667,6.651) AT24(-0.667,6.651) AT27(-1.772,6.651) AT29(-2.953,6.55) AT31(-4.071,6.55) AT33(-4.985,6.499) AT36(-6.663,6.311) AU7(7.936,6.994) AU35(-6.077,7.084) AU36(-6.713,6.938) AU39(-7.991,7.141) AV6(8.237,7.645) AV11(6.068,7.396) AV13(5.087,7.232) AV15(4.096,7.388) AV17(2.953,7.413) AV19(1.772,7.413) AV22(0.667,7.413) AV24(-0.667,7.413) AV27(-1.772,7.413) AV29(-2.953,7.312) AV31(-4.071,7.312) AV33(-4.985,7.261) AW9(7.141,7.991) AW11(6.068,8.158) AW13(5.087,7.994) AW15(4.096,8.15) AW17(2.953,8.175) AW19(1.772,8.175) AW22(0.667,8.175) AW24(-0.667,8.175) AW27(-1.772,8.175) AW29(-2.953,8.074) AW31(-4.071,8.074) AW33(-5.036,8.023) AW35(-6.037,7.999) AW37(-6.994,7.936) AY5(8.764,8.585) AY38(-7.645,8.237) B1(10.814,-10.46) B2(10.33,-10.33) B3(9.824,-10.326) B43(-9.8,-10.304) B44(-10.33,-10.33) B45(-10.814,-10.46) BA40(-8.585,8.764) BB1(10.814,9.459) BB45(-10.814,9.459) BC1(10.814,9.959) BC2(10.326,9.824) BC44(-10.304,9.8) BC45(-10.814,9.959) BD1(10.814,10.46) BD2(10.33,10.33) BD3(9.8,10.304) BD43(-9.824,10.326) BD44(-10.33,10.33) BD45(-10.814,10.46) BE2(10.46,10.814) BE3(9.959,10.814) BE4(9.459,10.814) BE42(-9.459,10.814) BE43(-9.959,10.814) BE44(-10.46,10.814) C1(10.814,-9.959) C2(10.304,-9.8) C42(-9.288,-9.86) C44(-10.326,-9.824) C45(-10.814,-9.959) D1(10.814,-9.459) D45(-10.814,-9.459) F8(7.645,-8.237) G9(6.994,-7.936) G11(6.037,-7.999) G13(5.036,-8.023) G15(4.071,-8.074) G17(2.953,-8.074) G19(1.772,-8.175) G22(0.667,-8.175) G24(-0.667,-8.175) G27(-1.772,-8.175) G29(-2.953,-8.175) G31(-4.096,-8.15) G33(-5.087,-7.994) G35(-6.068,-8.158) G37(-7.141,-7.991) H13(4.985,-7.261) H15(4.071,-7.312) H17(2.953,-7.312) H19(1.772,-7.413) H22(0.667,-7.413) H24(-0.667,-7.413) H27(-1.772,-7.413) H29(-2.953,-7.413) H31(-4.096,-7.388) H33(-5.087,-7.232) H35(-6.068,-7.396) J7(7.991,-7.141) J10(6.713,-6.938) J11(6.077,-7.084) J39(-7.936,-6.994) K10(6.663,-6.311) K13(4.985,-6.499) K15(4.071,-6.55) K17(2.953,-6.55) K19(1.772,-6.651) K22(0.667,-6.651) K24(-0.667,-6.651) K27(-1.772,-6.651) K29(-2.953,-6.651) K31(-4.096,-6.626) K33(-5.087,-6.47) K36(-6.311,-6.663) K37(-6.938,-6.713) L7(8.158,-6.068) L8(7.396,-6.068) L12(5.551,-6.04) L13(5.026,-5.753) L15(4.071,-5.788) L17(2.953,-5.788) L19(1.772,-5.889) L22(0.667,-5.889) L24(-0.667,-5.889) L27(-1.772,-5.889) L29(-2.953,-5.889) L31(-4.096,-5.864) L37(-7.084,-6.077) L39(-7.999,-6.037) M35(-6.04,-5.551) N7(7.994,-5.087) N8(7.232,-5.087) N10(6.47,-5.087) N15(4.071,-5.026) N17(2.953,-5.026) N19(1.772,-5.127) N22(0.667,-5.127) N24(-0.667,-5.127) N27(-1.772,-5.127) N29(-2.953,-5.127) N31(-4.096,-5.102) N35(-5.753,-5.026) N36(-6.499,-4.985) N38(-7.261,-4.985) N39(-8.023,-5.036) P17(2.953,-4.315) P19(1.772,-4.365) P22(0.667,-4.365) P24(-0.667,-4.365) P27(-1.772,-4.365) P29(-2.953,-4.365) P31(-4.096,-4.34) R7(8.15,-4.096) R8(7.388,-4.096) R10(6.626,-4.096) R11(5.864,-4.096) R13(5.102,-4.096) R14(4.34,-4.096) R17(2.953,-3.807) R19(1.772,-3.807) R22(0.667,-3.807) R24(-0.667,-3.807) R27(-1.772,-3.807) R29(-2.953,-3.807) R33(-5.026,-4.071) R35(-5.788,-4.071) R36(-6.55,-4.071) R38(-7.312,-4.071) R39(-8.074,-4.071) U7(8.175,-2.953) U8(7.413,-2.953) U10(6.651,-2.953) U11(5.889,-2.953) U13(5.127,-2.953) U14(4.365,-2.953) U15(3.807,-2.953) U17(3.099,-3.099) U18(2.324,-3.099) U20(1.549,-3.099) U21(0.775,-3.099) U23(0,-3.099) U25(-0.775,-3.099) U26(-1.549,-3.099) U28(-2.324,-3.099) U29(-3.099,-3.099) U31(-3.807,-2.953) U32(-4.315,-2.953) U33(-5.026,-2.953) U35(-5.788,-2.953) U36(-6.55,-2.953) U38(-7.312,-2.953) U39(-8.074,-2.953) V17(3.099,-2.324) V18(2.324,-2.324) V20(1.549,-2.324) V21(0.775,-2.324) V23(0,-2.324) V25(-0.775,-2.324) V26(-1.549,-2.324) V28(-2.324,-2.324) V29(-3.099,-2.324) W7(8.175,-1.772) W8(7.413,-1.772) W10(6.651,-1.772) W11(5.889,-1.772) W13(5.127,-1.772) W14(4.365,-1.772) W15(3.807,-1.772) W31(-3.807,-1.772) W32(-4.365,-1.772) W33(-5.127,-1.772) W35(-5.889,-1.772) W36(-6.651,-1.772) W38(-7.413,-1.772) W39(-8.175,-1.772) Y17(3.099,-1.549) Y18(2.324,-1.549) Y20(1.549,-1.549) Y21(0.775,-1.549) Y23(0,-1.549) Y25(-0.775,-1.549) Y26(-1.549,-1.549) Y28(-2.324,-1.549) Y29(-3.099,-1.549)
  round 0.279 smd: A5(8.959,-10.814) A41(-8.959,-10.814) BA1(10.814,8.959) BA45(-10.814,8.959) BE5(8.959,10.814) BE41(-8.959,10.814) E1(10.814,-8.959) E45(-10.814,-8.959)
  round 0.254 smd: A6(8.458,-10.814) A25(-1.225,-10.814) A40(-8.458,-10.814) AB3(9.888,-0.609) AB4(9.403,-0.482) AB5(8.937,-0.667) AB41(-8.937,-0.667) AB42(-9.421,-0.509) AC3(9.727,-0.096) AD3(9.929,0.484) AD4(9.421,0.509) AD5(8.937,0.667) AD41(-8.937,0.667) AD42(-9.403,0.482) AF3(9.888,1.664) AF5(8.885,1.721) AF41(-8.887,1.721) AG3(9.727,2.178) AG4(9.403,1.791) AG42(-9.421,1.764) AJ4(9.421,2.783) AJ5(8.836,2.953) AJ41(-8.937,2.953) AJ42(-9.403,2.756) AL3(9.888,3.937) AL4(9.403,4.064) AL5(8.836,4.071) AL41(-8.887,4.096) AL42(-9.421,4.037) AM3(9.727,4.451) AN3(9.929,5.03) AN4(9.421,5.056) AN5(8.785,5.163) AN41(-8.756,5.087) AN42(-9.403,5.029) AR5(8.886,6.182) AR41(-8.92,6.068) AT4(9.403,6.338) AT42(-9.421,6.311) AU41(-9.038,7.09) AU43(-9.727,6.915) AV3(9.929,7.355) AV4(9.229,7.321) AV43(-9.888,7.391) AW4(9.434,8.204) AW42(-9.24,7.816) AY1(10.814,8.458) AY45(-10.814,8.458) B6(8.45,-10.296) B10(6.724,-10.235) B25(-1.225,-10.306) B40(-8.701,-10.355) BA4(9.602,9.12) BA5(8.767,9.095) BA9(7.09,9.038) BA11(6.068,8.92) BA13(5.087,8.756) BA15(4.096,8.887) BA17(2.953,8.937) BA20(1.721,8.887) BA22(0.667,8.937) BA24(-0.667,8.937) BA26(-1.721,8.885) BA29(-2.953,8.836) BA31(-4.071,8.836) BA33(-5.163,8.785) BA35(-6.182,8.886) BA41(-9.095,8.767) BB3(10.162,9.344) BB7(7.816,9.24) BB10(6.311,9.421) BB13(5.029,9.403) BB15(4.037,9.421) BB17(2.756,9.403) BB19(1.764,9.421) BB22(0.482,9.403) BB24(-0.509,9.421) BB27(-1.791,9.403) BB29(-2.783,9.421) BB31(-4.064,9.403) BB33(-5.056,9.421) BB36(-6.338,9.403) BB38(-7.321,9.229) BB39(-8.204,9.434) BB41(-9.12,9.602) BB43(-9.86,9.288) BC4(9.288,9.86) BC9(6.915,9.727) BC42(-9.344,10.162) BE6(8.458,10.814) BE40(-8.458,10.814) C8(7.355,-9.929) C10(6.724,-9.727) C11(6.211,-9.888) C14(4.451,-9.727) C15(3.937,-9.888) C17(2.757,-9.929) C19(2.178,-9.727) C20(1.664,-9.888) C23(-0.096,-9.727) C24(-0.609,-9.888) C27(-1.789,-9.929) C28(-2.369,-9.727) C29(-2.883,-9.888) C31(-4.063,-9.929) C32(-4.642,-9.727) C33(-5.156,-9.888) C36(-6.336,-9.929) C37(-6.915,-9.727) C38(-7.391,-9.888) D3(9.86,-9.288) D5(9.12,-9.602) D7(8.204,-9.434) D8(7.321,-9.229) D10(6.338,-9.403) D13(5.056,-9.421) D15(4.064,-9.403) D17(2.783,-9.421) D19(1.791,-9.403) D22(0.509,-9.421) D24(-0.482,-9.403) D27(-1.764,-9.421) D29(-2.756,-9.403) D31(-4.037,-9.421) D33(-5.029,-9.403) D36(-6.311,-9.421) D39(-7.816,-9.24) D43(-10.162,-9.344) E5(9.095,-8.767) E6(8.585,-8.764) E11(6.182,-8.886) E13(5.163,-8.785) E15(4.071,-8.836) E17(2.953,-8.836) E20(1.721,-8.885) E22(0.667,-8.937) E24(-0.667,-8.937) E26(-1.721,-8.887) E29(-2.953,-8.937) E31(-4.096,-8.887) E33(-5.087,-8.756) E35(-6.068,-8.92) E37(-7.09,-9.038) E41(-8.767,-9.095) E42(-9.602,-9.12) F1(10.814,-8.458) F41(-8.764,-8.585) F44(-10.296,-8.45) F45(-10.814,-8.458) G4(9.24,-7.816) G42(-9.434,-8.204) H2(10.396,-7.391) H3(9.888,-7.391) H40(-8.237,-7.645) H42(-9.229,-7.321) H43(-9.929,-7.355) J2(10.235,-6.915) J3(9.727,-6.915) J5(9.038,-7.09) K2(10.428,-6.432) K3(9.929,-6.336) K4(9.421,-6.311) K42(-9.403,-6.338) K43(-9.727,-6.724) L5(8.92,-6.068) L41(-8.886,-6.182) L43(-9.888,-6.211) N3(9.888,-5.156) N4(9.403,-5.029) N5(8.756,-5.087) N41(-8.785,-5.163) N42(-9.421,-5.056) P3(9.727,-4.642) R4(9.421,-4.037) R5(8.887,-4.096) R41(-8.836,-4.071) R42(-9.403,-4.064) U3(9.888,-2.883) U4(9.403,-2.756) U5(8.937,-2.953) U41(-8.836,-2.953) U42(-9.421,-2.783) V3(9.727,-2.369) W3(9.929,-1.789) W4(9.421,-1.764) W42(-9.403,-1.791) Y5(8.887,-1.721) Y41(-8.885,-1.721)
  oval 0.203x0.254 smd: A7(7.893,-10.814) A9(6.852,-10.814) A37(-6.839,-10.814) A39(-7.893,-10.814) B7(7.944,-10.306) B39(-7.944,-10.306) BC8(7.391,9.888) BD6(8.701,10.355) BD7(7.944,10.306) BD36(-6.724,10.235) BD39(-7.944,10.306) BE7(7.893,10.814) BE9(6.839,10.814) BE37(-6.852,10.814) BE39(-7.893,10.814)
  oval 0.152x0.254 smd: A12(5.595,-10.814) A14(4.553,-10.814) A16(3.321,-10.814) A18(2.28,-10.814) A21(1.048,-10.814) A23(0.007,-10.814) A28(-2.267,-10.814) A32(-4.54,-10.814) B8(7.258,-10.428) B11(6.211,-10.396) B13(4.934,-10.428) B15(3.937,-10.396) B18(2.661,-10.428) B19(2.178,-10.235) B20(1.664,-10.396) B22(0.388,-10.428) B24(-0.609,-10.396) B27(-1.886,-10.428) B33(-5.156,-10.396) B36(-6.432,-10.428) BD10(6.432,10.428) BD13(5.156,10.396) BD14(4.642,10.235) BD15(4.159,10.428) BD17(2.883,10.396) BD18(2.369,10.235) BD19(1.886,10.428) BD22(0.609,10.396) BD23(0.096,10.235) BD24(-0.388,10.428) BD26(-1.664,10.396) BD27(-2.178,10.235) BD28(-2.661,10.428) BD31(-3.937,10.396) BD32(-4.451,10.235) BD33(-4.934,10.428) BD35(-6.211,10.396) BD38(-7.258,10.428) BE11(5.772,10.814) BE14(4.54,10.814) BE16(3.499,10.814) BE18(2.267,10.814) BE21(1.225,10.814) BE23(-0.007,10.814) BE25(-1.048,10.814) BE28(-2.28,10.814) BE30(-3.321,10.814) BE32(-4.553,10.814) BE34(-5.595,10.814)
  custom 0.051x0.051 smd: A30(-3.499,-10.814) A35(-5.772,-10.814) AA2(10.306,-1.225) AA44(-10.306,-1.048) AB43(-9.929,-0.484) AD43(-9.888,0.609) AE2(10.306,1.048) AE44(-10.306,1.225) AG43(-9.929,1.789) AJ3(9.929,2.757) AJ43(-9.888,2.883) AK2(10.306,3.321) AK44(-10.306,3.499) AL43(-9.929,4.063) AM2(10.235,4.451) AN43(-9.888,5.156) AP2(10.306,5.595) AR3(9.888,6.211) AR44(-10.306,5.772) AT43(-9.929,6.336) AU44(-10.235,6.915) AV44(-10.396,7.391) B12(5.595,-10.306) B14(4.451,-10.235) B16(3.321,-10.306) B21(1.048,-10.306) B23(-0.096,-10.235) B29(-2.883,-10.396) B30(-3.499,-10.306) B31(-4.159,-10.428) B32(-4.642,-10.235) B35(-5.772,-10.306) B37(-6.915,-10.235) B38(-7.391,-10.396) BC10(6.336,9.929) BC13(5.156,9.888) BC15(4.063,9.929) BC17(2.883,9.888) BC19(1.789,9.929) BC22(0.609,9.888) BC24(-0.484,9.929) BC26(-1.664,9.888) BC29(-2.757,9.929) BC31(-3.937,9.888) BC33(-5.03,9.929) BC35(-6.211,9.888) BC38(-7.355,9.929) BD8(7.391,10.396) BD9(6.915,10.235) BD11(5.772,10.306) BD16(3.499,10.306) BD21(1.225,10.306) BD25(-1.048,10.306) BD30(-3.321,10.306) BD34(-5.595,10.306) C13(5.03,-9.929) C22(0.484,-9.929) L2(10.306,-5.772) M44(-10.306,-5.595) N43(-9.929,-5.03) P2(10.235,-4.642) R2(10.428,-4.159) R3(9.929,-4.063) R43(-9.888,-3.937) T1(10.814,-3.499) T2(10.306,-3.499) T44(-10.306,-3.321) U2(10.396,-2.883) U43(-9.929,-2.757) V2(10.235,-2.369) Y43(-9.888,-1.664)
  oval 0.254x0.152 smd: AA1(10.814,-1.225) AA45(-10.814,-1.048) AB2(10.396,-0.609) AB44(-10.428,-0.388) AC1(10.814,0.007) AC2(10.235,-0.096) AC44(-10.235,0.096) AC45(-10.814,-0.007) AD2(10.428,0.388) AD44(-10.396,0.609) AE1(10.814,1.048) AE45(-10.814,1.225) AF2(10.396,1.664) AG2(10.235,2.178) AG44(-10.428,1.886) AH1(10.814,2.28) AH2(10.428,2.661) AH44(-10.235,2.369) AH45(-10.814,2.267) AJ44(-10.396,2.883) AK1(10.814,3.321) AK45(-10.814,3.499) AL2(10.396,3.937) AL44(-10.428,4.159) AM1(10.814,4.553) AM44(-10.235,4.642) AM45(-10.814,4.54) AN2(10.428,4.934) AN44(-10.396,5.156) AP1(10.814,5.595) AR2(10.396,6.211) AR45(-10.814,5.772) AT44(-10.428,6.432) AV2(10.428,7.258) L1(10.814,-5.772) L44(-10.396,-6.211) M45(-10.814,-5.595) N2(10.396,-5.156) N44(-10.428,-4.934) P1(10.814,-4.54) P44(-10.235,-4.451) P45(-10.814,-4.553) R44(-10.396,-3.937) T45(-10.814,-3.321) V1(10.814,-2.267) V44(-10.428,-2.661) V45(-10.814,-2.28) W2(10.428,-1.886) W44(-10.235,-2.178) Y44(-10.396,-1.664)
  round 0.368 smd: AA4(9.326,-1.225) AA42(-9.324,-1.048) AE4(9.324,1.048) AE42(-9.326,1.225) AK4(9.324,3.321) AK42(-9.326,3.499) AP4(9.324,5.595) AR42(-9.326,5.772) AY2(10.296,8.45) BB11(5.772,9.326) BB16(3.499,9.326) BB21(1.225,9.326) BB25(-1.048,9.324) BB30(-3.321,9.324) BB34(-5.595,9.324) BD40(-8.45,10.296) C4(9.344,-10.162) D12(5.595,-9.324) D16(3.321,-9.324) D21(1.048,-9.324) D25(-1.225,-9.326) D30(-3.499,-9.326) D35(-5.772,-9.326) L4(9.326,-5.772) M42(-9.324,-5.595) T4(9.326,-3.499) T42(-9.324,-3.321)
  custom 0.057x0.057 smd: AC43(-9.727,0.096) AH43(-9.727,2.369) AM43(-9.727,4.642) AT3(9.727,6.724) B28(-2.369,-10.235) BC14(4.642,9.727) BC18(2.369,9.727) BC23(0.096,9.727) BC27(-2.178,9.727) BC32(-4.451,9.727) BC36(-6.724,9.727) P43(-9.727,-4.451) W43(-9.727,-2.178)
  oval 0.254x0.203 smd: AT2(10.235,6.724) AU1(10.814,6.852) AU45(-10.814,6.839) AW1(10.814,7.893) AW2(10.306,7.944) AW44(-10.306,7.944) AW45(-10.814,7.893) AY44(-10.355,8.701) F2(10.355,-8.701) G1(10.814,-7.893) G2(10.306,-7.944) G44(-10.306,-7.944) G45(-10.814,-7.893) H44(-10.428,-7.258) J1(10.814,-6.839) J45(-10.814,-6.852) K44(-10.235,-6.724)
BUZZER_1
  round 1.372 hole 0.914: N(3.251,0) P(-3.251,0)
C0402_2
  oval 0.572x0.508 smd: 1(-0.476,0) 2(0.476,0)
C0603_2
  oval 0.889x0.762 smd: 1(-0.699,0) 2(0.699,0)
C0603_4D7UF
  oval 0.991x0.864 smd: 1(-0.699,0) 2(0.699,0)
C0805_2
  oval 1.016x1.397 smd: 1(-0.889,0) 2(0.889,0)
C7343_1
  rect 2.55x2.9 smd: 1(-3.125,0) 2(3.125,0)
CHOKE-APL0806P-R60M
  round 1.981 hole 1.524: 1(-2.25,2.2)
  oval 2.438x1.981 hole 1.981x1.524 rot 135: 2(2.25,-2.2)
CHOKE_1R0M_1
  round 1.778 hole 1.321: 1(-2.2,2.25)
  oval 1.778x2.235 hole 1.321x1.778 rot 45: 2(2.2,-2.25)
CHOKE_2R2M_PT6D6X6D6MM
  round 1.981 hole 1.524: 1(-3.3,3.3)
  oval 2.438x1.981 hole 1.981x1.524 rot 135: 2(3.3,-3.3)
CHOKE_3R3M_PT5MM_SMD
  rect 2x2.5 smd: 1(-2.5,0) 2(2.5,0)
CHOKE_PT6D2MM_SMD_2P
  rect 2.5x3.5 smd: 1(-3.1,0) 2(3.1,0)
CHOKE_R30_PT6D3X1D4MM_1
  round 2.286 hole 1.829: 1(3.15,0.7)
  oval 2.286x2.743 hole 1.829x2.286 rot 135: 2(-3.15,-0.7)
CMM21_1
  rect 0.45x0.9 smd: 1(-0.425,0.85) 2(-0.425,-0.85) 3(0.425,-0.85) 4(0.425,0.85)
CON6X1_2D5MM-PINREX
  rect 1.372x1.372 hole 1.016: 1(-6.25,-0.525)
  round 1.372 hole 1.016: 2(-3.75,-0.525) 3(-1.25,-0.525) 4(1.25,-0.525) 5(3.75,-0.525) 6(6.25,-0.525)
CON10X2_2MM_20P_USB3_1
  rect 1.168x1.168 hole 0.813: 1(-9,1)
  round 1.168 hole 0.813: 2(-7,1) 3(-5,1) 4(-3,1) 5(-1,1) 6(1,1) 7(3,1) 8(5,1) 9(7,1) 10(9,1) 11(9,-1) 12(7,-1) 13(5,-1) 14(3,-1) 15(1,-1) 16(-1,-1) 17(-3,-1) 18(-5,-1) 19(-7,-1)
CRYSTAL_1
  round 1.067 hole 0.711: 1(-2.54,0) 2(2.54,0)
  round 0.813 hole 0.508: 3(0,0)
CRYSTAL_PT4D88MM-AT49_2
  round 1.219 hole 0.838: 1(-2.44,0) 2(2.44,0)
  round 0.813 hole 0.508: 3(0,0)
D-SUB_15P-HDR-HT
  round 1.473 smd: (-8.91,-2.63) (-7.765,-0.63) (-6.62,-2.63) (5.975,-0.63) (7.12,1.37) (7.12,-2.63)
  round 1.473 hole 1.067: 1(-4.33,-2.63) 2(-2.04,-2.63) 3(0.25,-2.63) 4(2.54,-2.63) 5(4.83,-2.63) 6(-5.475,-0.63) 7(-3.185,-0.63) 8(-0.895,-0.63) 9(1.395,-0.63) 10(3.685,-0.63) 11(-4.33,1.37) 12(-2.04,1.37) 13(0.25,1.37) 14(2.54,1.37) 15(4.83,1.37)
  round 3.607 hole 3.251: 16(-12.495,-0.63) 17(12.495,-0.63)
DDR4_288P_1
  round 2.438 hole 2.438 unplated: (2.7,5.659) (2.7,-132.291)
  oval 2.438x1.194 hole 2.438x1.194 unplated: (2.7,-68.891)
  rect 0.965x0.965 hole 0.66: 1(0,0)
  round 0.965 hole 0.66: 2(1.6,-0.85) 3(0,-1.7) 4(1.6,-2.55) 5(0,-3.4) 6(1.6,-4.249) 7(0,-5.099) 8(1.6,-5.949) 9(0,-6.799) 10(1.6,-7.649) 11(0,-8.499) 12(1.6,-9.349) 13(0,-10.199) 14(1.6,-11.048) 15(0,-11.898) 16(1.6,-12.748) 17(0,-13.598) 18(1.6,-14.448) 19(0,-15.298) 20(1.6,-16.148) 21(0,-16.998) 22(1.6,-17.848) 23(0,-18.697) 24(1.6,-19.547) 25(0,-20.397) 26(1.6,-21.247) 27(0,-22.097) 28(1.6,-22.947) 29(0,-23.797) 30(1.6,-24.647) 31(0,-25.497) 32(1.6,-26.346) 33(0,-27.196) 34(1.6,-28.046) 35(0,-28.896) 36(1.6,-29.746) 37(0,-30.596) 38(1.6,-31.446) 39(0,-32.296) 40(1.6,-33.145) 41(0,-33.995) 42(1.6,-34.845) 43(0,-35.695) 44(1.6,-36.545) 45(0,-37.395) 46(1.6,-38.245) 47(0,-39.095) 48(1.6,-39.945) 49(0,-40.794) 50(1.6,-41.644) 51(0,-42.494) 52(1.6,-43.344) 53(0,-44.194) 54(1.6,-45.044) 55(0,-45.894) 56(1.6,-46.744) 57(0,-47.594) 58(1.6,-48.443) 59(0,-49.293) 60(1.6,-50.143) 61(0,-50.993) 62(1.6,-51.843) 63(0,-52.693) 64(1.6,-53.543) 65(0,-54.393) 66(1.6,-55.242) 67(0,-56.092) 68(1.6,-56.942) 69(0,-57.792) 70(1.6,-58.642) 71(0,-59.492) 72(1.6,-60.342) 73(0,-61.192) 74(1.6,-62.042) 75(0,-62.891) 76(1.6,-63.741) 77(0,-64.591) 78(1.6,-70.54) 79(0,-71.39) 80(1.6,-72.24) 81(0,-73.09) 82(1.6,-73.94) 83(0,-74.79) 84(1.6,-75.64) 85(0,-76.49) 86(1.6,-77.339) 87(0,-78.189) 88(1.6,-79.039) 89(0,-79.889) 90(1.6,-80.739) 91(0,-81.589) 92(1.6,-82.439) 93(0,-83.289) 94(1.6,-84.139) 95(0,-84.988) 96(1.6,-85.838) 97(0,-86.688) 98(1.6,-87.538) 99(0,-88.388) 100(1.6,-89.238) 101(0,-90.088) 102(1.6,-90.938) 103(0,-91.787) 104(1.6,-92.637) 105(0,-93.487) 106(1.6,-94.337) 107(0,-95.187) 108(1.6,-96.037) 109(0,-96.887) 110(1.6,-97.737) 111(0,-98.587) 112(1.6,-99.436) 113(0,-100.286) 114(1.6,-101.136) 115(0,-101.986) 116(1.6,-102.836) 117(0,-103.686) 118(1.6,-104.536) 119(0,-105.386) 120(1.6,-106.236) 121(0,-107.085) 122(1.6,-107.935) 123(0,-108.785) 124(1.6,-109.635) 125(0,-110.485) 126(1.6,-111.335) 127(0,-112.185) 128(1.6,-113.035) 129(0,-113.884) 130(1.6,-114.734) 131(0,-115.584) 132(1.6,-116.434) 133(0,-117.284) 134(1.6,-118.134) 135(0,-118.984) 136(1.6,-119.834) 137(0,-120.684) 138(1.6,-121.533) 139(0,-122.383) 140(1.6,-123.233) 141(0,-124.083) 142(1.6,-124.933) 143(0,-125.783) 144(1.6,-126.633) 145(3.8,0) 146(5.4,-0.85) 147(3.8,-1.7) 148(5.4,-2.55) 149(3.8,-3.4) 150(5.4,-4.249) 151(3.8,-5.099) 152(5.4,-5.949) 153(3.8,-6.799) 154(5.4,-7.649) 155(3.8,-8.499) 156(5.4,-9.349) 157(3.8,-10.199) 158(5.4,-11.048) 159(3.8,-11.898) 160(5.4,-12.748) 161(3.8,-13.598) 162(5.4,-14.448) 163(3.8,-15.298) 164(5.4,-16.148) 165(3.8,-16.998) 166(5.4,-17.848) 167(3.8,-18.697) 168(5.4,-19.547) 169(3.8,-20.397) 170(5.4,-21.247) 171(3.8,-22.097) 172(5.4,-22.947) 173(3.8,-23.797) 174(5.4,-24.647) 175(3.8,-25.497) 176(5.4,-26.346) 177(3.8,-27.196) 178(5.4,-28.046) 179(3.8,-28.896) 180(5.4,-29.746) 181(3.8,-30.596) 182(5.4,-31.446) 183(3.8,-32.296) 184(5.4,-33.145) 185(3.8,-33.995) 186(5.4,-34.845) 187(3.8,-35.695) 188(5.4,-36.545) 189(3.8,-37.395) 190(5.4,-38.245) 191(3.8,-39.095) 192(5.4,-39.945) 193(3.8,-40.794) 194(5.4,-41.644) 195(3.8,-42.494) 196(5.4,-43.344) 197(3.8,-44.194) 198(5.4,-45.044) 199(3.8,-45.894) 200(5.4,-46.744) 201(3.8,-47.594) 202(5.4,-48.443) 203(3.8,-49.293) 204(5.4,-50.143) 205(3.8,-50.993) 206(5.4,-51.843) 207(3.8,-52.693) 208(5.4,-53.543) 209(3.8,-54.393) 210(5.4,-55.242) 211(3.8,-56.092) 212(5.4,-56.942) 213(3.8,-57.792) 214(5.4,-58.642) 215(3.8,-59.492) 216(5.4,-60.342) 217(3.8,-61.192) 218(5.4,-62.042) 219(3.8,-62.891) 220(5.4,-63.741) 221(3.8,-64.591) 222(5.4,-70.54) 223(3.8,-71.39) 224(5.4,-72.24) 225(3.8,-73.09) 226(5.4,-73.94) 227(3.8,-74.79) 228(5.4,-75.64) 229(3.8,-76.49) 230(5.4,-77.339) 231(3.8,-78.189) 232(5.4,-79.039) 233(3.8,-79.889) 234(5.4,-80.739) 235(3.8,-81.589) 236(5.4,-82.439) 237(3.8,-83.289) 238(5.4,-84.139) 239(3.8,-84.988) 240(5.4,-85.838) 241(3.8,-86.688) 242(5.4,-87.538) 243(3.8,-88.388) 244(5.4,-89.238) 245(3.8,-90.088) 246(5.4,-90.938) 247(3.8,-91.787) 248(5.4,-92.637) 249(3.8,-93.487) 250(5.4,-94.337) 251(3.8,-95.187) 252(5.4,-96.037) 253(3.8,-96.887) 254(5.4,-97.737) 255(3.8,-98.587) 256(5.4,-99.436) 257(3.8,-100.286) 258(5.4,-101.136) 259(3.8,-101.986) 260(5.4,-102.836) 261(3.8,-103.686) 262(5.4,-104.536) 263(3.8,-105.386) 264(5.4,-106.236) 265(3.8,-107.085) 266(5.4,-107.935) 267(3.8,-108.785) 268(5.4,-109.635) 269(3.8,-110.485) 270(5.4,-111.335) 271(3.8,-112.185) 272(5.4,-113.035) 273(3.8,-113.884) 274(5.4,-114.734) 275(3.8,-115.584) 276(5.4,-116.434) 277(3.8,-117.284) 278(5.4,-118.134) 279(3.8,-118.984) 280(5.4,-119.834) 281(3.8,-120.684) 282(5.4,-121.533) 283(3.8,-122.383) 284(5.4,-123.233) 285(3.8,-124.083) 286(5.4,-124.933) 287(3.8,-125.783) 288(5.4,-126.633)
